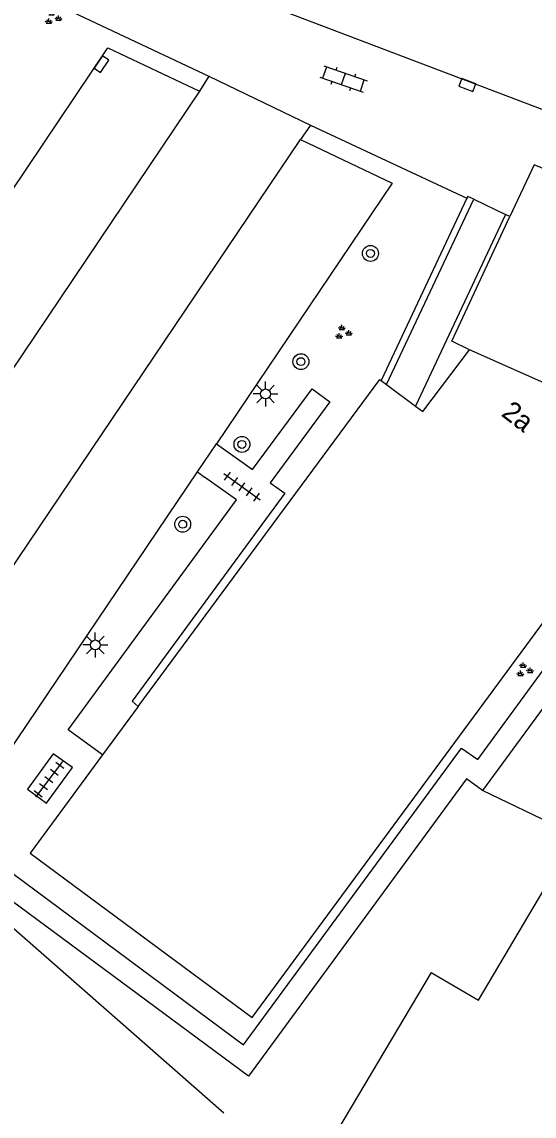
# Model space of a CAD drawing. Extents: x 136000 to 141014, y 402000 to 403500.
# Drawn here: x 137884.6 to 137910.3, y 402559.1 to 402614.1 of the extents above; entities that cross this region are included whole.
import ezdxf

# ---------------------------------------------------------------- set-up
doc = ezdxf.new("R2010")
doc.units = 0
for name, color, linetype in [('gg-afsc-erfafscheiding', 7, 'Continuous'), ('gg-afsc-muur', 7, 'Continuous'), ('gg-anno-huisnummerreeks BGT', 7, 'Continuous'), ('gg-bbg-gedigitaliseerde bebouwing', 7, 'Continuous'), ('gg-bbg-hoofdgebouw', 7, 'Continuous'), ('gg-bbg-tussenscheiding', 7, 'Continuous'), ('gg-knt-verharding', 7, 'Continuous'), ('gg-knt-verharding nz', 7, 'Continuous'), ('gt-symb-boom', 7, 'Continuous'), ('gt-symb-groenvak', 7, 'Continuous'), ('gt-symb-klinker verharding', 7, 'Continuous'), ('gt-symb-kolk', 7, 'Continuous'), ('gt-symb-lichtmast', 7, 'Continuous'), ('gt-symb-tegel verharding', 7, 'Continuous')]:
    doc.layers.add(name, color=color, linetype=linetype)

# ---------------------------------------------------------------- blocks, each defined once
blk = doc.blocks.new('gt0-KOLK')
at = {"layer": 'gt-symb-kolk'}
blk.add_lwpolyline([(0, 0), (0.375, 0), (0.375, 0.4), (-0.375, 0.4), (-0.375, 0), (0, 0)], dxfattribs=at)
blk = doc.blocks.new('gt0-GRVAK')
at = {"layer": 'gt-symb-groenvak'}
for p, q in [((-0.11, 0.189), (-0.228, 0.24)), ((-0.182, 0.153), (0.088, 0.153)), ((-0.091, 0.211), (-0.156, 0.322)), ((-0.047, 0.214), (-0.047, 0.393)), ((-0.004, 0.211), (0.061, 0.322)), ((0.015, 0.189), (0.133, 0.24)), ((0.262, -0.052), (0.197, 0.059)), ((0.305, -0.049), (0.305, 0.13)), ((0.349, -0.052), (0.414, 0.059)), ((-0.245, -0.228), (-0.363, -0.177)), ((-0.318, -0.264), (-0.047, -0.264)), ((-0.226, -0.206), (-0.291, -0.095)), ((-0.183, -0.203), (-0.183, -0.024)), ((-0.139, -0.206), (-0.074, -0.095)), ((-0.12, -0.228), (-0.002, -0.177)), ((0.243, -0.074), (0.125, -0.023)), ((0.17, -0.11), (0.441, -0.11)), ((0.368, -0.074), (0.486, -0.023))]:
    blk.add_line(p, q, dxfattribs=at)
blk = doc.blocks.new('gt0-LMAST')
at = {"layer": 'gt-symb-lichtmast'}
for p, q in [((-0.005, 0.246), (-0.005, 0.621)), ((-0.182, 0.173), (-0.447, 0.438)), ((0.172, 0.173), (0.437, 0.438)), ((-0.255, -0.004), (-0.63, -0.004)), ((-0.182, -0.181), (-0.447, -0.446)), ((-0.005, -0.254), (-0.005, -0.629)), ((0.437, -0.446), (0.172, -0.181)), ((0.245, -0.004), (0.62, -0.004))]:
    blk.add_line(p, q, dxfattribs=at)
blk.add_circle((-0.005, -0.004), 0.25, dxfattribs=at)
blk = doc.blocks.new('gt0-BOOM')
at = {"layer": 'gt-symb-boom'}
for radius in [0.4, 0.2]:
    blk.add_circle((0, 0), radius, dxfattribs=at)
blk = doc.blocks.new('gt0-KL1')
at = {"layer": 'gt-symb-klinker verharding'}
for p, q in [((-1.15, 0.3), (1.15, 0.3)), ((-1, -0.3), (-1, 0.3)), ((-0.5, 0.3), (-0.5, 0.45)), ((0, -0.3), (0, 0.3)), ((0.5, 0.3), (0.5, 0.45)), ((1, -0.3), (1, 0.3)), ((-1.15, -0.3), (1.15, -0.3)), ((-0.5, -0.45), (-0.5, -0.3)), ((0.5, -0.45), (0.5, -0.3))]:
    blk.add_line(p, q, dxfattribs=at)
blk = doc.blocks.new('gt0-TEG1')
at = {"layer": 'gt-symb-tegel verharding'}
for p, q in [((-1.125, 0), (1.125, 0)), ((-0.9, -0.25), (-0.9, 0.25)), ((-0.45, -0.25), (-0.45, 0.25)), ((0, -0.25), (0, 0.25)), ((0.45, -0.25), (0.45, 0.25)), ((0.9, -0.25), (0.9, 0.25))]:
    blk.add_line(p, q, dxfattribs=at)

msp = doc.modelspace()

# ---------------------------------------------------------------- linework, layer by layer
at = {"layer": 'gg-afsc-erfafscheiding'}
msp.add_line((137913.813, 402572.508), (137907.754, 402575.442), dxfattribs=at)
msp.add_lwpolyline([(137894.752, 402559.219), (137883.232, 402569.318), (137879.666, 402572.509), (137855.808, 402585.474)], dxfattribs=at)
at = {"layer": 'gg-afsc-muur'}
for p, q in [((137906.972, 402605.215), (137902.662, 402596.056)), ((137902.927, 402595.859), (137907.321, 402605.168)), ((137907.016, 402605.309), (137906.972, 402605.215)), ((137907.321, 402605.168), (137907.016, 402605.309)), ((137908.91, 402604.4), (137904.391, 402594.767)), ((137909.134, 402604.294), (137908.91, 402604.4))]:
    msp.add_line(p, q, dxfattribs=at)
at = {"layer": 'gg-bbg-gedigitaliseerde bebouwing'}
msp.add_line((137905.17, 402566.29), (137899, 402555.887), dxfattribs=at)
at = {"layer": 'gg-bbg-hoofdgebouw'}
for p, q in [((137902.662, 402596.056), (137902.927, 402595.859)), ((137902.927, 402595.859), (137904.391, 402594.767)), ((137890.449, 402579.66), (137888.659, 402577.235))]:
    msp.add_line(p, q, dxfattribs=at)
for points in [[(137935.38, 402596.66), (137910.35, 402606.9), (137909.134, 402604.294)], [(137907.1, 402597.6), (137906.21, 402598.03), (137909.134, 402604.294)], [(137904.391, 402594.767), (137904.75, 402594.5), (137907.1, 402597.6)], [(137890.449, 402579.66), (137902.59, 402596.11), (137902.662, 402596.056)], [(137888.659, 402577.235), (137885.01, 402572.29), (137896.18, 402564.031), (137913.74, 402587.86)], [(137905.17, 402566.29), (137907.55, 402564.89), (137911.37, 402571.35), (137916.73, 402568.18), (137916.221, 402567.319)]]:
    msp.add_lwpolyline(points, dxfattribs=at)
at = {"layer": 'gg-bbg-tussenscheiding'}
msp.add_line((137914.99, 402594.09), (137907.1, 402597.6), dxfattribs=at)
at = {"layer": 'gg-knt-verharding'}
for p, q in [((137886.048, 402615.099), (137893.991, 402611.351)), ((137893.991, 402611.351), (137893.522, 402610.597)), ((137893.991, 402611.351), (137899.115, 402608.892)), ((137899.115, 402608.892), (137898.602, 402608.166)), ((137899.115, 402608.892), (137906.972, 402605.215)), ((137907.321, 402605.168), (137908.91, 402604.4)), ((137893.425, 402591.457), (137894.387, 402592.875)), ((137882.235, 402574.858), (137893.425, 402591.457)), ((137893.425, 402591.457), (137893.781, 402591.201)), ((137913.912, 402583.839), (137907.754, 402575.442))]:
    msp.add_line(p, q, dxfattribs=at)
for points in [[(137896.524, 402615.103), (137924.24, 402604.562), (137929.766, 402602.381), (137934.402, 402600.357)], [(137873.458, 402580.783), (137869.272, 402583.602), (137875.771, 402593.347), (137880.76, 402600.64), (137888.916, 402612.779), (137893.522, 402610.597)], [(137898.602, 402608.166), (137903.207, 402605.973), (137894.387, 402592.875)], [(137894.387, 402592.875), (137896.194, 402591.586), (137899.19, 402595.637), (137900.077, 402594.986), (137897.09, 402590.917), (137897.818, 402590.395), (137890.142, 402579.929), (137890.449, 402579.66)], [(137888.659, 402577.235), (137886.935, 402578.496), (137895.393, 402590.062), (137893.781, 402591.201)], [(137877.222, 402576.39), (137895.746, 402562.657), (137906.702, 402577.561), (137907.514, 402576.993), (137912.996, 402584.497)], [(137887.149, 402576.598), (137886.178, 402577.284), (137884.883, 402575.508), (137885.833, 402574.804), (137887.149, 402576.598)], [(137907.754, 402575.442), (137906.944, 402576.033), (137896, 402561.076), (137883.678, 402570.188), (137876.6, 402575.481)]]:
    msp.add_lwpolyline(points, dxfattribs=at)
at = {"layer": 'gg-knt-verharding nz'}
for p, q in [((137893.522, 402610.597), (137873.458, 402580.783)), ((137878.062, 402577.686), (137898.602, 402608.166))]:
    msp.add_line(p, q, dxfattribs=at)

# ---------------------------------------------------------------- block references
at = {"layer": 'gt-symb-boom'}
for p in [(137902.123, 402602.445), (137898.629, 402597.002), (137895.664, 402592.842), (137892.684, 402588.828)]:
    msp.add_blockref('gt0-BOOM', p, dxfattribs=at)
at = {"layer": 'gt-symb-groenvak'}
for p in [(137886.142, 402614.285), (137900.737, 402598.462), (137909.846, 402581.49)]:
    msp.add_blockref('gt0-GRVAK', p, dxfattribs=at)
at = {"layer": 'gt-symb-klinker verharding', "rotation": -19.214311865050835}
msp.add_blockref('gt0-KL1', (137900.769, 402611.22), dxfattribs=at)
at = {"layer": 'gt-symb-kolk'}
for p, rotation in [((137888.438, 402612.069), -123.91251258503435), ((137907.064, 402611.099), 159.20120552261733)]:
    msp.add_blockref('gt0-KOLK', p, dxfattribs=dict(at, rotation=rotation))
at = {"layer": 'gt-symb-lichtmast'}
for p in [(137896.854, 402595.383), (137888.297, 402582.761)]:
    msp.add_blockref('gt0-LMAST', p, dxfattribs=at)
at = {"layer": 'gt-symb-tegel verharding'}
for p, rotation in [((137895.67, 402590.714), -35.724134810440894), ((137885.962, 402575.997), -127.15637415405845)]:
    msp.add_blockref('gt0-TEG1', p, dxfattribs=dict(at, rotation=rotation))

# ---------------------------------------------------------------- texts
at = {"layer": 'gg-anno-huisnummerreeks BGT'}
msp.add_text('2a', height=1, rotation=322.8, dxfattribs=at).set_placement((137908.649, 402594.31))

doc.saveas('drawing.dxf')
